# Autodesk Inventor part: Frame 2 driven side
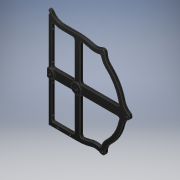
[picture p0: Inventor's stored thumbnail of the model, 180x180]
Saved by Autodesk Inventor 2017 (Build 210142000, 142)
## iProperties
Created: 2016-06
Part Number: Frame 2 driven side
Material: Generic
Document SubType Name: Modeling
Designer: Stan
Density: 1 g/cm^3
Appearance: Glossy - Black
Author: Stan
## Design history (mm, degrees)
sketch "Sketch1"
  geometry: L1 (-33.07, 98.425)-(0, 98.425); L2 (-33.07, 88.9)-(-9.525, 88.9); L3 (-60.566, -98.425)-(0, -98.425); L4 (-51.041, -9.525)-(-9.525, -9.525); L5 (9.525, -9.525)-(85.613, -9.525); L6 (-51.041, 9.525)-(-9.525, 9.525); L7 (9.525, 9.525)-(85.613, 9.525); L8 (-51.041, -88.9)-(-9.525, -88.9); L9 (-6.35, -12.7)-(-6.35, -85.725); L10 (6.35, -12.7)-(6.35, -85.194); L11 (-6.35, 12.7)-(-6.35, 85.725); L12 (6.35, 12.7)-(6.35, 85.194); L13 (-60.566, 114.3)-(-60.566, 110.49); L14 (-60.566, 105.41)-(-60.566, -98.425); L15 (-54.216, 90.23)-(-54.216, 12.7); L16 (-54.216, -12.7)-(-54.216, -85.725); C1 r 2.54 at (104.775, 0); C2 r 2.54 at (52.387, -90.738); C3 r 2.54 at (52.388, 90.738); C4 r 1.984 at (0, 0); A1 r 3.175 centre (-9.525, 85.725) between (-6.35, 85.725) and (-9.525, 88.9); A2 r 3.175 centre (-51.041, -12.7) between (-51.041, -9.525) and (-54.216, -12.7); A3 r 3.175 centre (-9.525, -12.7) between (-6.35, -12.7) and (-9.525, -9.525); A4 r 3.175 centre (-9.525, 12.7) between (-9.525, 9.525) and (-6.35, 12.7); A5 r 3.175 centre (9.525, 12.7) between (6.35, 12.7) and (9.525, 9.525); A6 r 98.425 centre (0, 0) between (0, -98.425) and (29.099, -94.025); A7 r 98.425 centre (0, 0) between (66.878, -72.213) and (95.978, -21.812); A8 r 98.425 centre (0, 0) between (95.978, 21.812) and (66.878, 72.213); A9 r 98.425 centre (0, 0) between (29.099, 94.025) and (0, 98.425); A10 r 88.9 centre (0, 0) between (9.878, -88.35) and (26.283, -84.926); A11 r 88.9 centre (0, 0) between (60.406, -65.225) and (86.69, -19.701); A12 r 3.175 centre (9.525, -85.194) between (6.35, -85.194) and (9.878, -88.35); A13 r 88.9 centre (0, 0) between (86.69, 19.701) and (60.406, 65.225); A14 r 88.9 centre (0, 0) between (26.283, 84.926) and (9.878, 88.35); A15 r 3.175 centre (9.525, 85.194) between (9.878, 88.35) and (6.35, 85.194); A16 r 6.35 centre (104.775, 0) between (107.969, -5.488) and (107.969, 5.488); A17 r 25.4 centre (120.746, 27.441) between (95.978, 21.812) and (107.969, 5.488); A18 r 34.925 centre (120.746, 27.441) between (86.69, 19.701) and (88.541, 13.928); A19 r 3.175 centre (85.613, 12.7) between (85.613, 9.525) and (88.541, 13.928); A20 r 25.4 centre (120.746, -27.441) between (107.969, -5.488) and (95.978, -21.812); A21 r 34.925 centre (120.746, -27.441) between (88.541, -13.928) and (86.69, -19.701); A22 r 3.175 centre (85.613, -12.7) between (88.541, -13.928) and (85.613, -9.525); A23 r 6.35 centre (52.387, -90.738) between (49.232, -96.248) and (58.737, -90.76); A24 r 25.4 centre (84.137, -90.849) between (66.878, -72.213) and (58.737, -90.76); A25 r 34.925 centre (84.137, -90.849) between (60.406, -65.225) and (50.239, -82.443); A26 r 25.4 centre (36.609, -118.29) between (49.232, -96.248) and (29.099, -94.025); A27 r 34.925 centre (36.609, -118.29) between (46.278, -84.73) and (26.283, -84.926); A28 r 3.175 centre (47.157, -81.679) between (46.278, -84.73) and (50.239, -82.443); A29 r 6.35 centre (52.388, 90.738) between (58.737, 90.76) and (49.232, 96.248); A30 r 25.4 centre (36.609, 118.29) between (29.099, 94.025) and (49.232, 96.248); A31 r 34.925 centre (36.609, 118.29) between (26.283, 84.926) and (46.278, 84.73); A32 r 25.4 centre (84.137, 90.849) between (58.737, 90.76) and (66.878, 72.213); A33 r 34.925 centre (84.137, 90.849) between (50.239, 82.443) and (60.406, 65.225); A34 r 3.175 centre (47.157, 81.679) between (50.239, 82.443) and (46.278, 84.73); A35 r 6.35 centre (-60.566, 107.95) between (-55.067, 111.125) and (-60.566, 114.3); A36 r 25.4 centre (-33.07, 123.825) between (-55.067, 111.125) and (-33.07, 98.425); A37 r 34.925 centre (-33.07, 123.825) between (-49.544, 93.029) and (-33.07, 88.9); A38 r 3.175 centre (-51.041, 90.23) between (-49.544, 93.029) and (-54.216, 90.23); A39 r 2.54 centre (-60.566, 107.95) between (-60.566, 105.41) and (-60.566, 110.49); A40 r 3.175 centre (-9.525, -85.725) between (-9.525, -88.9) and (-6.35, -85.725); A41 r 3.175 centre (9.525, -12.7) between (9.525, -9.525) and (6.35, -12.7); A42 r 3.175 centre (-51.041, 12.7) between (-54.216, 12.7) and (-51.041, 9.525); A43 r 3.175 centre (-51.041, -85.725) between (-54.216, -85.725) and (-51.041, -88.9); 1 further point
  constraints: 86 point on circle, 47 centre point, 32 end point
extrude "Extrusion1" new body sketch "Sketch1" distance "d0" = 6.35; taper "d1" = 0 deg
fillet "Fillet1" dims "d2" = 0.79375
sketch "Sketch2"
  geometry: L1 (0, 0)-(0, 203.835) reference; C1 r 1.587 at (3.175, 177.8); C2 r 1.587 at (3.175, 117.475); C3 r 1.587 at (3.175, 79.375); C4 r 1.587 at (3.175, 19.05); 3 further points
  constraints: 4 centre point
  dimensions: "d3" = 3.175 diameter of C1; "d4" = 3.175 diameter of C2; "d5" = 3.175 diameter of C3; "d6" = 3.175 diameter of C4; "d7" = 3.175 distance from line of L1 C1.centre; "d8" = 3.175 distance from line of L1 C2.centre; "d9" = 3.175 distance from line of L1 C3.centre; "d10" = 3.175 distance from line of L1 C4.centre; "d11" = 60.325 distance of C3.centre C4.centre; "d12" = 9.525 vertical distance of C3.centre point (5.556, 88.9); "d13" = 9.525 vertical distance of C2.centre point (5.556, 107.95); "d14" = 60.325 distance of C2.centre C1.centre
extrude "Extrusion2" cut sketch "Sketch2" distance "d15" = 6.35; taper "d16" = 0 deg
sketch "Sketch4"
  geometry: C1 r 3.175 at (-56.385, -0.006); 1 further point
  constraints: 1 centre point
  dimensions: "d23" = 56.38546 distance of point (0, 0) C1.centre
extrude "Extrusion4" cut sketch "Sketch4" distance "d21" = 6.35; taper "d22" = 0 deg
sketch "Sketch5"
  geometry: L1 (-60.566, 105.41)-(-60.566, -97.631) reference; L2 (-60.566, -8.887)-(-60.566, 8.874); C1 r 3.175 at (-56.385, -0.006) reference; C2 r 3.175 at (-56.385, -0.006); A1 r 9.816 centre (-56.385, -0.006) between (-60.566, -8.887) and (-60.566, 8.874); A2 r 3.969 centre (-51.041, 12.7) between (-55.01, 12.7) and (-51.041, 8.731) reference; 1 further point
  constraints: 2 centre point, 2 coincident, 2 end point, 2 point on circle, 2 point on line, 1 concentric, 1 tangent
fillet "Fillet2" dims "d24" = 0.79375
extrude "Extrusion5" join sketch "Sketch5" distance "d25" = 3.175; taper "d26" = 0 deg
sketch "Sketch6"
  geometry: C1 r 11.113 at (0, 0); C2 r 1.984 at (0, 0); 1 further point
  constraints: 2 centre point, 2 coincident
  dimensions: "d27" = 22.225 diameter of C1
extrude "Extrusion6" join sketch "Sketch6" distance "d28" = 3.175; taper "d29" = 0 deg
fillet "Fillet3" dims "d30" = 0.79375
sketch "Sketch7"
  geometry: L1 (-60.566, -8.887)-(-60.566, -97.631) reference; L2 (-60.566, -98.425)-(0, -98.425) reference; C1 r 2.54 at (-41.516, -93.663); C2 r 2.54 at (-16.116, -93.663); 1 further point
  constraints: 2 centre point
  dimensions: "d31" = 5.08 diameter of C1; "d32" = 5.08 diameter of C2; "d33" = 19.05 distance from line of L1 C1.centre; "d34" = 25.4 distance of C2.centre C1.centre; "d35" = 4.7625 distance from line of L2 C1.centre; "d36" = 4.7625 distance from line of L2 C2.centre
extrude "Extrusion7" cut sketch "Sketch7" distance "d37" = 6.35; taper "d38" = 0 deg
sketch "Sketch8"
  geometry: C1 r 3.572 at (0, 0); 1 further point
  constraints: 1 centre point, 1 coincident
  dimensions: "d39" = 7.14375 diameter of C1
extrude "Extrusion8" cut sketch "Sketch8" distance "d40" = 9.525; taper "d41" = 0 deg
body "Solid1"
